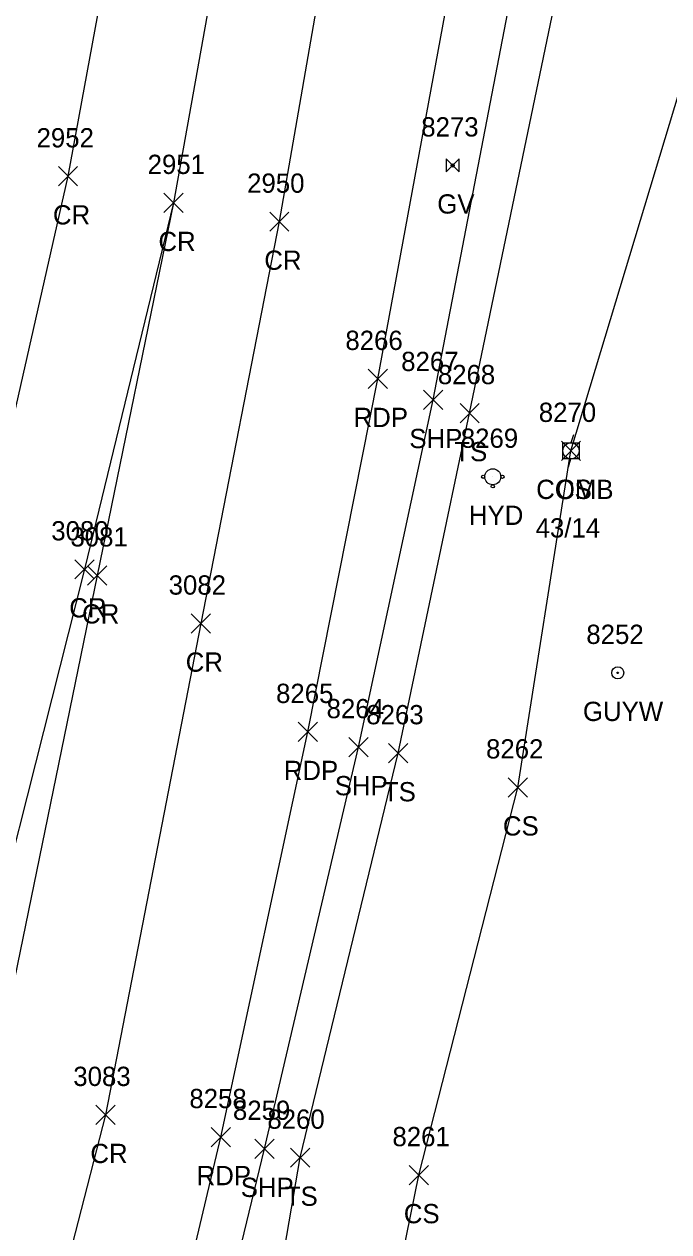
# Model space of a CAD drawing. Extents: x 1462089 to 1464015, y 730534 to 736144.
# Drawn here: x 1463139 to 1463205.9, y 733147.7 to 733273.1 of the extents above; entities that cross this region are included whole.
import ezdxf

# ---------------------------------------------------------------- set-up
doc = ezdxf.new("R2010")
doc.units = 0
for name, color, linetype in [('L_A', 7, 'Continuous'), ('L_I', 7, 'Continuous'), ('L_TIC', 7, 'Continuous'), ('LELB', 7, 'Continuous'), ('P_A', 7, 'Continuous'), ('P_I', 7, 'Continuous'), ('P_TIC', 7, 'Continuous'), ('PET', 7, 'Continuous'), ('PRC', 7, 'Continuous'), ('PSP', 7, 'Continuous'), ('U_A', 7, 'Continuous'), ('U_C', 7, 'Continuous'), ('U_I', 7, 'Continuous'), ('UP', 7, 'Continuous'), ('UPGW', 7, 'Continuous'), ('UWFH', 7, 'Continuous'), ('UWV', 7, 'Continuous')]:
    doc.layers.add(name, color=color, linetype=linetype)

msp = doc.modelspace()

# ---------------------------------------------------------------- linework, layer by layer
at = {"layer": 'L_TIC'}
for points in [[(1463184.25, 733231.7), (1463186.25, 733233.7)], [(1463186.25, 733231.7), (1463184.25, 733233.7)], [(1463194.76, 733227.78), (1463196.76, 733229.78)], [(1463196.76, 733227.78), (1463194.76, 733229.78)], [(1463176.84, 733196.39), (1463178.84, 733198.39)], [(1463178.84, 733196.39), (1463176.84, 733198.39)], [(1463189.26, 733192.84), (1463191.26, 733194.84)], [(1463191.26, 733192.84), (1463189.26, 733194.84)], [(1463166.67, 733154.4), (1463168.67, 733156.4)], [(1463168.67, 733154.4), (1463166.67, 733156.4)], [(1463178.98, 733152.59), (1463180.98, 733154.59)], [(1463180.98, 733152.59), (1463178.98, 733154.59)]]:
    msp.add_lwpolyline(points, dxfattribs=at)
at = {"layer": 'LELB'}
for points in [[(1463159, 733047.79), (1463156.76, 733059.91), (1463160.64, 733073.64), (1463169.65, 733102.67), (1463179.98, 733153.59), (1463190.26, 733193.84), (1463195.76, 733228.78), (1463210.63, 733278.18), (1463221.02, 733316.85), (1463223.3, 733370.09), (1463228.7, 733397.04), (1463238.14, 733460.73), (1463234.6, 733504.05), (1463240.97, 733543.72), (1463245.95, 733585.02), (1463248.18, 733630.7), (1463252.73, 733683.16), (1463258.26, 733734.47), (1463266.55, 733743.22), (1463277.96, 733752.98), (1463292.82, 733753.9)], [(1463187.25, 733038.06), (1463169.97, 733042.76), (1463159, 733047.79), (1463151.09, 733051.08), (1463143.18, 733058.72), (1463159.23, 733106.04), (1463167.67, 733155.4), (1463177.84, 733197.39), (1463185.25, 733232.7), (1463195.06, 733279.97), (1463202.53, 733320.84), (1463210.95, 733372.16), (1463215.01, 733399.27), (1463224.35, 733462.44)]]:
    msp.add_lwpolyline(points, dxfattribs=at)
at = {"layer": 'P_TIC'}
for points in [[(1463142.59, 733256.28), (1463144.59, 733258.28)], [(1463144.59, 733256.28), (1463142.59, 733258.28)], [(1463153.54, 733253.52), (1463155.54, 733255.52)], [(1463155.54, 733253.52), (1463153.54, 733255.52)], [(1463153.54, 733253.52), (1463155.54, 733255.52)], [(1463155.54, 733253.52), (1463153.54, 733255.52)], [(1463164.51, 733251.57), (1463166.51, 733253.57)], [(1463166.51, 733251.57), (1463164.51, 733253.57)], [(1463174.72, 733235.25), (1463176.72, 733237.25)], [(1463176.72, 733235.25), (1463174.72, 733237.25)], [(1463180.46, 733233.06), (1463182.46, 733235.06)], [(1463182.46, 733233.06), (1463180.46, 733235.06)], [(1463144.29, 733215.48), (1463146.29, 733217.48)], [(1463146.29, 733215.48), (1463144.29, 733217.48)], [(1463145.61, 733214.85), (1463147.61, 733216.85)], [(1463147.61, 733214.85), (1463145.61, 733216.85)], [(1463156.36, 733209.85), (1463158.36, 733211.85)], [(1463158.36, 733209.85), (1463156.36, 733211.85)], [(1463167.48, 733198.6), (1463169.48, 733200.6)], [(1463169.48, 733198.6), (1463167.48, 733200.6)], [(1463172.72, 733197.02), (1463174.72, 733199.02)], [(1463174.72, 733197.02), (1463172.72, 733199.02)], [(1463146.48, 733158.84), (1463148.48, 733160.84)], [(1463148.48, 733158.84), (1463146.48, 733160.84)], [(1463158.44, 733156.54), (1463160.44, 733158.54)], [(1463160.44, 733156.54), (1463158.44, 733158.54)], [(1463162.97, 733155.32), (1463164.97, 733157.32)], [(1463164.97, 733155.32), (1463162.97, 733157.32)]]:
    msp.add_lwpolyline(points, dxfattribs=at)
at = {"layer": 'PET'}
msp.add_lwpolyline([(1463023.48, 732671), (1463036.19, 732713.31), (1463039.97, 732724.95), (1463046.42, 732748.22), (1463045.94, 732761.16), (1463059.87, 732803.81), (1463070.46, 732836.88), (1463084.18, 732884.08), (1463100.27, 732939.23), (1463111.27, 732977.09), (1463121.46, 733012.56), (1463135.84, 733063.71), (1463147.86, 733108.52), (1463159.44, 733157.54), (1463168.48, 733199.6), (1463175.72, 733236.25), (1463184.37, 733283.25), (1463191.27, 733323.49), (1463191.08, 733323.84), (1463204.04, 733400.9), (1463213.28, 733462.86)], dxfattribs=at)
at = {"layer": 'PRC'}
for points in [[(1463173.05, 733431.97), (1463166.54, 733387.93), (1463158.95, 733340.73), (1463152.26, 733304.55), (1463143.59, 733257.28), (1463135.29, 733220.7), (1463120.9, 733164.91), (1463101.36, 733098.43), (1463088.62, 733051.16), (1463070, 732996.41), (1463055.29, 732948.06), (1463043.07, 732909.01), (1463027.36, 732860.42), (1463013.91, 732819.27), (1462999.18, 732769.26), (1462985.72, 732731.93), (1462969.44, 732677.27)], [(1463184.26, 733428.99), (1463177.5, 733386.21), (1463169.42, 733335), (1463162.87, 733301.13), (1463154.54, 733254.52), (1463145.29, 733216.48), (1463131.67, 733162.65), (1463112.82, 733093.24), (1463099.08, 733044.74), (1463082.5, 732993.09), (1463066.93, 732944.79), (1463054.22, 732905.14), (1463038.5, 732856.13), (1463025.08, 732814.55), (1463009.9, 732766.25), (1462997.49, 732727.73), (1462980.34, 732670.55), (1462968.82, 732637.25), (1462956.14, 732592.49), (1462943.23, 732555.63), (1462933.85, 732526.13), (1462921.41, 732485.16), (1462905.69, 732440.94), (1462895.98, 732404.53)], [(1463173.56, 733299.02), (1463165.51, 733252.57), (1463157.36, 733210.85), (1463147.48, 733159.84), (1463128.56, 733086.33), (1463116.13, 733039.22), (1463100.45, 732983.58), (1463087.95, 732938.84), (1463073.8, 732896.76), (1463059.6, 732849.78), (1463047.56, 732806.21), (1463032.36, 732758.17), (1463016.83, 732714.7), (1463001.87, 732663.36), (1462991.08, 732629.32), (1462977.35, 732584.7), (1462966.06, 732548.54), (1462956.48, 732518.6), (1462941.54, 732474.04), (1462928.1, 732429.75), (1462916.12, 732396.98)], [(1463154.54, 733254.52), (1463146.61, 733215.85), (1463135.44, 733161.47), (1463118.39, 733090.76), (1463105.83, 733042.87), (1463089.37, 732989.24), (1463076.43, 732943.44), (1463063.88, 732901.54), (1463049.78, 732852.76), (1463036.58, 732810.58), (1463021.66, 732763.56), (1463007.35, 732718.7), (1462991.11, 732667.44), (1462980.42, 732633.72), (1462966.43, 732588.15), (1462955.05, 732551.99), (1462945.51, 732521.94), (1462931.54, 732478.17), (1462917.14, 732435.42), (1462906.01, 732400.46)]]:
    msp.add_lwpolyline(points, dxfattribs=at)
at = {"layer": 'PSP'}
msp.add_lwpolyline([(1463046.42, 732748.22), (1463053.17, 732770.64), (1463063.86, 732801.92), (1463074.6, 732835.37), (1463088.19, 732883.02), (1463104.54, 732937.8), (1463115.69, 732976.25), (1463126.02, 733011.46), (1463140.26, 733061.84), (1463152.14, 733107.42), (1463163.97, 733156.32), (1463173.72, 733198.02), (1463181.46, 733234.06), (1463190.45, 733280.83), (1463197.61, 733321.61), (1463206.08, 733372.72), (1463210.25, 733399.69), (1463219.8, 733463.02)], dxfattribs=at)
at = {"layer": 'UP'}
for p, q in [((1463196.01, 733230.44), (1463195.76, 733229.61)), ((1463194.93, 733227.94), (1463194.93, 733229.61)), ((1463194.93, 733229.61), (1463196.6, 733229.61)), ((1463196.6, 733229.61), (1463196.6, 733227.94)), ((1463196.6, 733227.94), (1463194.93, 733227.94)), ((1463195.51, 733227.11), (1463195.76, 733227.94)), ((1463195.76, 733228.78), (1463195.76, 733228.78))]:
    msp.add_line(p, q, dxfattribs=at)
msp.add_circle((1463195.76, 733228.78), 0.833, dxfattribs=at)
at = {"layer": 'UPGW'}
for radius in [0.625, 0.0833]:
    msp.add_circle((1463200.61, 733205.73), radius, dxfattribs=at)
at = {"layer": 'UWFH'}
msp.add_line((1463187.65, 733226.09), (1463187.65, 733226.09), dxfattribs=at)
for centre, radius in [((1463187.65, 733226.09), 0.833), ((1463186.65, 733226.09), 0.167), ((1463187.65, 733225.09), 0.167), ((1463188.65, 733226.09), 0.167)]:
    msp.add_circle(centre, radius, dxfattribs=at)
at = {"layer": 'UWV'}
for p, q in [((1463182.82, 733259.08), (1463184.16, 733257.74)), ((1463184.16, 733259.08), (1463182.82, 733257.74))]:
    msp.add_line(p, q, dxfattribs=at)
for points in [[(1463182.82, 733259.08), (1463182.82, 733257.74)], [(1463184.16, 733257.74), (1463184.16, 733259.08)]]:
    msp.add_lwpolyline(points, dxfattribs=at)
msp.add_circle((1463183.49, 733258.41), 0.167, dxfattribs=at)

# ---------------------------------------------------------------- texts
at = {"layer": 'L_A'}
for s, p in [('TS', (1463183.66, 733227.7)), ('CS', (1463194.2, 733223.78)), ('TS', (1463176.25, 733192.39)), ('CS', (1463188.7, 733188.84)), ('TS', (1463166.08, 733150.4)), ('CS', (1463178.42, 733148.59))]:
    msp.add_text(s, height=2, dxfattribs=at).set_placement(p)
at = {"layer": 'L_I'}
for s, p in [('8268', (1463181.95, 733235.7)), ('8270', (1463192.42, 733231.78)), ('8263', (1463174.53, 733200.39)), ('8262', (1463186.95, 733196.84)), ('8260', (1463164.27, 733158.4)), ('8261', (1463177.24, 733156.59))]:
    msp.add_text(s, height=2, dxfattribs=at).set_placement(p)
at = {"layer": 'P_A'}
for s, p in [('CR', (1463142.03, 733252.28)), ('CR', (1463152.97, 733249.52)), ('CR', (1463152.97, 733249.52)), ('CR', (1463163.95, 733247.57)), ('RDP', (1463173.21, 733231.25)), ('SHP', (1463178.99, 733229.06)), ('CR', (1463143.72, 733211.48)), ('CR', (1463145.05, 733210.85)), ('CR', (1463155.8, 733205.85)), ('RDP', (1463165.97, 733194.6)), ('SHP', (1463171.26, 733193.02)), ('CR', (1463145.91, 733154.84)), ('RDP', (1463156.93, 733152.54)), ('SHP', (1463161.51, 733151.32))]:
    msp.add_text(s, height=2, dxfattribs=at).set_placement(p)
at = {"layer": 'P_I'}
for s, p in [('2952', (1463140.33, 733260.28)), ('2951', (1463151.85, 733257.52)), ('2951', (1463151.85, 733257.52)), ('2950', (1463162.17, 733255.57)), ('8266', (1463172.36, 733239.25)), ('8267', (1463178.15, 733237.06)), ('3080', (1463141.86, 733219.48)), ('3081', (1463143.84, 733218.85)), ('3082', (1463154.03, 733213.85)), ('8265', (1463165.17, 733202.6)), ('8264', (1463170.41, 733201.02)), ('3083', (1463144.14, 733162.84)), ('8258', (1463156.18, 733160.54)), ('8259', (1463160.7, 733159.32))]:
    msp.add_text(s, height=2, dxfattribs=at).set_placement(p)
at = {"layer": 'U_A'}
for s, p in [('GV', (1463181.89, 733253.41)), ('COMB', (1463192.15, 733223.78)), ('HYD', (1463185.17, 733221.09)), ('GUYW', (1463197, 733200.73))]:
    msp.add_text(s, height=2, dxfattribs=at).set_placement(p)
at = {"layer": 'U_C'}
msp.add_text('43/14', height=2, dxfattribs=at).set_placement((1463192.09, 733219.78))
at = {"layer": 'U_I'}
for s, p in [('8273', (1463180.23, 733261.41)), ('8270', (1463192.42, 733231.78)), ('8269', (1463184.33, 733229.09)), ('8252', (1463197.35, 733208.73))]:
    msp.add_text(s, height=2, dxfattribs=at).set_placement(p)

doc.saveas('drawing.dxf')
